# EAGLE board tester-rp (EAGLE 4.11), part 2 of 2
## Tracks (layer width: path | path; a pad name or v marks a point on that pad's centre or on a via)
A1  (via drill 0.61)
  Top 0.254: A1-K1.1 66.04,56.5 67.31,55.23 JP3.1 | v74.93,51.42 74.93,48.24 SIDE1.10
  Bottom 0.254: 62.87,51.42 62.87,53.32 66.67,53.32 JP3.1 | 62.87,51.42 62.87,14.59 71.12,6.33 IN1-2.1 | 62.87,51.42 v74.93,51.42
A2  (via drill 0.61)
  Top 0.254: A2-K2.1 99.06,26.02 100.33,24.75 JP4.1 100.33,22.21 100.33,19.04 101.6,17.77 SIDE2.2 | v101.6,40.62 101.6,46.34 103.5,46.34 104.14,46.98 104.14,55.23 105.41,56.5 105.41,60.95 100.33,60.95 97.79,63.48 97.79,66.66 96.52,67.93 96.52,74.92 97.79,76.19 R1.2
  Bottom 0.254: v101.6,40.62 101.6,36.81 104.78,36.81 105.41,36.18 105.41,29.2 100.97,29.2 99.69,27.92 A2-K2.1
B1
  Top 0.254: A1-K1.2 68.58,56.5 69.85,55.23 JP3.2 69.85,52.69 69.85,48.24 SIDE1.6 69.85,46.98 68.58,45.7 68.58,44.44 72.39,40.62 72.39,7.6 73.66,6.33 IN1-2.3
B2
  Top 0.254: A2-K2.2 101.6,26.02 102.87,24.75 JP4.2 102.87,22.21 102.87,19.04 104.14,17.77 SIDE2.4
C1
  Top 0.254: A1-K1.3 71.12,56.5 72.39,55.23 JP3.3 72.39,52.69 71.12,51.42 71.12,45.07 | SIDE1.1 65.41,45.07 66.67,45.07 SIDE1.3 | 71.12,45.07 70.48,45.07 SIDE1.5 | 71.12,45.07 71.75,45.07 SIDE1.7 73.03,45.07 74.3,45.07 SIDE1.9 74.93,44.44 74.93,7.6 76.2,6.33 IN1-2.5 | SIDE1.17 85.72,45.07 87,45.07 SIDE1.19 88.27,45.07 89.53,45.07 SIDE1.21 90.81,45.07 92.08,45.07 SIDE1.23 93.34,45.07 94.62,45.07 SIDE1.25 95.89,45.07 97.16,45.07 SIDE1.27 98.43,45.07 99.69,45.07 SIDE1.29 | SIDE1.33 104.78,45.07 103.5,45.07 SIDE1.31
  Bottom 0.254: SIDE1.5 69.22,45.07 67.95,45.07 SIDE1.3 | SIDE1.9 75.56,45.07 76.84,45.07 SIDE1.11 78.11,45.07 79.38,45.07 SIDE1.13 80.65,45.07 81.92,45.07 SIDE1.15 83.19,45.07 84.45,45.07 SIDE1.17 | SIDE1.31 102.23,45.07 100.97,45.07 SIDE1.29
C2
  Top 0.254: A2-K2.3 104.14,26.02 105.41,24.75 JP4.3 105.41,22.21 105.41,14.59 | 105.41,14.59 104.78,14.59 SIDE2.3 | 105.41,14.59 106.05,14.59 SIDE2.5 107.31,14.59 108.59,14.59 SIDE2.7 109.86,14.59 111.12,14.59 SIDE2.9 | SIDE2.15 120.02,14.59 121.28,14.59 SIDE2.17 122.56,14.59 123.83,14.59 SIDE2.19 125.09,14.59 126.36,14.59 SIDE2.21 127.64,14.59 128.91,14.59 SIDE2.23 | SIDE2.25 132.72,14.59 133.99,14.59 SIDE2.27 135.25,14.59 136.53,14.59 SIDE2.29 137.8,14.59 139.06,14.59 SIDE2.31
  Bottom 0.254: SIDE2.1 102.23,14.59 103.5,14.59 SIDE2.3 | SIDE2.9 112.4,14.59 113.66,14.59 SIDE2.11 114.94,14.59 116.2,14.59 SIDE2.13 117.47,14.59 118.75,14.59 SIDE2.15 | SIDE2.25 131.44,14.59 130.18,14.59 SIDE2.23 | SIDE2.33 141.61,14.59 140.34,14.59 SIDE2.31
D1
  Top 0.254: 73.66,56.5 74.93,55.23 JP3.4 74.93,52.69 76.2,51.42 76.2,44.44 77.47,43.16 77.47,7.6 78.74,6.33 IN1-2.7 | 73.66,56.5 A1-K1.4 73.66,56.5 | 73.66,56.5 73.66,49.52 72.39,48.24 SIDE1.8
D2  (via drill 0.61)
  Top 0.254: A2-K2.4 106.68,26.02 107.95,24.75 JP4.4 107.95,22.21 106.68,20.94 106.68,17.77 SIDE2.6 | v100.33,15.86 100.33,7.6 99.06,6.33 IN3-4.3
  Bottom 0.254: v100.33,15.86 100.33,18.4 104.78,18.4 106.05,17.13 SIDE2.6
E1
  Top 0.254: IN1-2.2 71.12,8.88 63.5,16.49 63.5,57.77 65.41,59.68 76.2,59.68 76.2,59.04 A1-K1.5 76.2,56.5 77.47,55.23 JP3.5 77.47,52.69 77.47,48.24 SIDE1.12
E2  (via drill 0.61)
  Top 0.254: A2-K2.5 109.22,26.02 110.49,24.75 JP4.5 110.49,22.21 109.22,20.94 109.22,17.77 SIDE2.8 | v102.87,11.41 102.87,7.6 101.6,6.33 IN3-4.5
  Bottom 0.254: v102.87,11.41 105.41,13.95 105.41,15.86 107.31,15.86 108.59,17.13 SIDE2.8
F1
  Top 0.254: A1-K1.6 78.74,56.5 80.01,55.23 JP3.6 80.01,52.69 80.01,48.24 SIDE1.14
  Bottom 0.254: IN1-2.4 73.03,8.24 63.5,17.77 63.5,50.15 76.2,50.15 79.38,53.32 JP3.6
F2
  Top 0.254: A2-K2.6 111.76,26.02 113.03,24.75 JP4.6 113.03,22.21 111.76,20.94 111.76,17.77 SIDE2.10
  Bottom 0.254: IN3-4.7 104.14,6.33 105.41,7.6 105.41,12.68 109.22,12.68 110.49,13.95 110.49,17.13 111.12,17.13 SIDE2.10
GND  (via drill 0.61)
  Top 0.305: CORE-IO.11 78.11,81.9 76.2,83.81 CORE-IO.10 76.2,85.08 76.2,86.98 | 76.2,86.98 76.2,91.43 73.66,93.97 71.12,93.97 71.12,97.14 72.39,98.41 72.39,100.32 | 72.39,100.32 72.39,115.56 71.12,116.83 BYP1.2 | 72.39,100.32 v73.03,100.32 | C1.2 97.79,86.35 96.52,87.62 96.52,99.68 IC3.7 | A2-K2.16 104.14,36.18 105.41,37.45 JP2.3 | L1-V1.12 106.68,66.66 105.41,67.93 JP1.16 105.41,70.47 104.14,71.74 104.14,88.89 102.23,88.89 100.97,87.62 IC9.7 | BYP7.2 125.09,76.82 125.09,60.95 123.83,59.68 IC7.7 123.19,58.41 v123.19,43.16 | v78.74,86.98 76.2,86.98
  Bottom 0.305: 73.03,100.95 80.01,100.95 81.28,99.68 IC2.7 | 73.03,100.95 72.39,100.95 71.12,99.68 IC1.7 | 81.92,118.73 73.03,118.73 71.75,117.46 BYP1.2 | 81.92,118.73 83.19,117.46 BYP2.2 | 94.62,118.73 95.89,117.46 BYP3.2 | 81.92,118.73 94.62,118.73 | 107.31,118.73 108.59,117.46 BYP4.2 | 94.62,118.73 107.31,118.73 | 120.02,118.73 121.28,117.46 BYP5.2 | 107.31,118.73 120.02,118.73 | 120.02,118.73 132.72,118.73 133.99,117.46 BYP6.2 | v73.03,100.32 73.03,100.95 | IC6.7 132.08,99.68 130.81,98.41 123.19,98.41 121.92,99.68 IC5.7 119.38,99.68 118.11,98.41 113.03,98.41 111.76,99.68 109.22,99.68 IC4.7 106.68,99.68 105.41,98.41 97.79,98.41 96.52,99.68 IC3.7 | C1.2 98.43,85.71 99.06,86.35 99.69,86.35 IC9.7 99.69,86.98 v78.74,86.98 | 84.45,15.22 83.82,15.22 BYP10.2 | 84.45,15.22 89.53,15.22 POWER.1 | 84.45,15.22 103.5,34.27 A2-K2.16 | 133.35,83.17 133.35,86.35 118.11,86.35 BYP9.2 | 133.35,83.17 133.35,81.27 137.16,77.46 BYP8.2 | IC8.7 134.62,59.04 133.35,60.31 125.73,60.31 124.46,59.04 IC7.7 122.56,59.68 111.12,59.68 106.68,64.12 L1-V1.12 | 133.35,83.17 128.91,83.17 128.27,82.54 128.27,80 127,80 124.46,77.46 BYP7.2 | v123.19,43.16 110.49,43.16 109.86,42.53 107.95,42.53 105.41,39.99 JP2.3
H1
  Top 0.254: A1-K1.7 81.28,56.5 82.55,55.23 JP3.7 82.55,52.69 82.55,48.24 SIDE1.16
  Bottom 0.254: IN1-2.6 76.2,7.6 74.93,6.33 74.93,4.43 70.48,4.43 62.23,12.68 62.23,55.87 79.38,55.87 80.65,57.13 A1-K1.7
H2
  Top 0.254: A2-K2.7 114.3,26.02 115.57,24.75 JP4.7 115.57,22.21 115.57,17.13 | 115.57,17.13 115.57,13.95 113.03,11.41 113.03,4.43 98.43,4.43 97.79,5.07 97.79,6.33 96.52,7.6 IN3-4.2 | 115.57,17.13 114.94,17.13 SIDE2.12
J1
  Top 0.254: 83.82,56.5 85.09,55.23 JP3.8 | 83.82,56.5 A1-K1.8 83.82,56.5 | 83.82,50.78 83.82,56.5 | 83.82,50.78 83.82,46.98 83.19,46.34 81.92,46.34 81.28,45.7 81.28,11.41 78.74,8.88 IN1-2.8 | 83.82,50.78 87,47.61 SIDE1.20
J2
  Top 0.254: A2-K2.8 116.84,26.02 118.11,24.75 JP4.8 118.11,22.21 118.11,19.04 116.84,17.77 SIDE2.14
  Bottom 0.254: IN3-4.4 99.06,8.88 99.06,12.68 98.43,13.32 98.43,25.38 114.94,25.38 116.2,26.65 A2-K2.8
K1  (via drill 0.61)
  Top 0.254: A1-K1.9 86.36,56.5 87.63,55.23 JP3.9 | v85.09,43.16 85.09,15.22 82.55,12.68 82.55,7.6 81.28,6.33 IN1-2.9
  Bottom 0.254: v85.09,43.16 86.36,44.44 86.36,46.98 85.09,46.98 SIDE1.18 85.72,47.61 87,48.88 87.63,48.88 87.63,52.69 JP3.9
K2
  Top 0.254: IN3-4.6 101.6,8.88 101.6,12.68 102.87,13.95 102.87,17.77 101.6,19.04 101.6,24.75 100.33,26.02 100.33,28.56 100.97,29.2 119.38,29.2 119.38,28.56 A2-K2.9 119.38,26.02 120.65,24.75 JP4.9 120.02,22.84 120.02,18.4 119.38,17.77 SIDE2.16
L1  (via drill 0.61)
  Top 0.254: L1-V1.1 91.44,56.5 90.17,55.23 JP3.10 90.17,52.69 92.71,50.15 92.71,48.24 SIDE1.24 | v90.17,6.97 91.44,8.24 v91.44,43.8
  Bottom 0.254: v90.17,6.97 85.72,6.97 84.45,5.7 IN1-2.11 | v91.44,43.8 91.44,47.61 92.08,47.61 SIDE1.24
L2
  Top 0.254: L2-V2.1 124.46,26.02 123.19,24.75 JP4.10 123.19,22.21 123.19,19.04 121.92,17.77 SIDE2.18
  Bottom 0.254: IN3-4.8 104.14,8.88 99.06,13.95 99.06,21.57 121.28,21.57 122.56,22.84 JP4.10
M1  (via drill 0.61)
  Top 0.254: L1-V1.2 93.98,56.5 92.71,55.23 JP3.11 92.71,52.69 97.16,48.24 97.16,47.61 SIDE1.28 | v87.63,35.55 87.63,7.6 86.36,6.33 IN1-2.13
  Bottom 0.254: v87.63,35.55 96.52,44.44 96.52,47.61 97.16,47.61 SIDE1.28
M2
  Top 0.254: L2-V2.2 127,26.02 125.73,24.75 JP4.11 125.73,22.21 125.73,19.04 124.46,17.77 SIDE2.20
  Bottom 0.254: IN3-4.9 107.31,5.7 109.86,3.16 139.06,3.16 143.51,7.6 143.51,21.57 127.64,21.57 126.36,22.84 JP4.11
MR\  (via drill 0.61)
  Top 0.254: v102.87,83.81 102.87,80.63 IC9.9
  Bottom 0.254: IC9.9 103.5,80 104.78,81.27 106.05,81.27 107.31,80 IC9.11 | v102.87,83.81 97.79,83.81 95.89,85.71 MR\.1
N1  (via drill 0.61)
  Top 0.254: L1-V1.3 96.52,56.5 95.25,55.23 JP3.12 | v93.98,43.8 93.98,5.7 89.53,5.7 IN1-2.15
  Bottom 0.254: 93.98,48.88 93.98,53.32 94.62,53.32 JP3.12 | v93.98,43.8 93.98,48.88 | 93.98,48.88 90.81,48.88 90.17,48.24 SIDE1.22
N2
  Top 0.254: L2-V2.3 129.54,26.02 128.27,24.75 JP4.12 128.27,22.21 127,20.94 127,17.77 SIDE2.22
  Bottom 0.254: IN3-4.11 109.22,6.33 110.49,7.6 110.49,11.41 123.19,11.41 125.73,13.95 125.73,17.13 126.36,17.13 SIDE2.22
N$1  (via drill 0.61)
  Top 0.254: v109.22,88.89 109.22,81.9 110.49,80.63 IC9.12
  Bottom 0.254: v109.22,88.89 106.68,88.89 106.68,85.71 106.05,85.08 104.78,85.08 103.5,86.35 IC9.6
N$2
  Bottom 0.254: IC9.4 108.59,86.35 109.86,86.35 IC9.3
N$5  (via drill 0.61)
  Top 0.254: v105.41,83.17 105.41,80.63 IC9.10
  Bottom 0.254: v105.41,83.17 104.78,82.54 100.33,82.54 98.43,80.63 C1.1 | R1.1 107.31,76.82 106.05,78.09 105.41,78.09 IC9.10
N$26
  Bottom 0.254: A5.L1 36.2,104.12 36.83,103.49 47.62,103.49 48.26,104.12 A9.L1
N$33
  Bottom 0.254: A5.L2 29.85,105.4 30.48,106.03 41.28,106.03 41.91,105.4 A9.L2
N$34
  Bottom 0.254: A5.M1 39.37,100.95 40.01,100.32 50.8,100.32 51.44,100.95 A9.M1
N$35
  Bottom 0.254: A5.M2 33.02,102.22 33.66,102.86 44.45,102.86 45.09,102.22 A9.M2
N$36
  Bottom 0.254: A5.N1 36.2,97.78 36.83,97.14 47.62,97.14 48.26,97.78 A9.N1
N$49
  Bottom 0.254: A5.N2 29.85,99.05 30.48,99.68 41.28,99.68 41.91,99.05 A9.N2
N$50
  Bottom 0.254: A5.P1 39.37,94.6 40.01,93.97 50.8,93.97 51.44,94.6 A9.P1
N$51
  Bottom 0.254: A5.P2 33.02,95.87 33.66,96.51 44.45,96.51 45.09,95.87 A9.P2
N$52
  Bottom 0.254: A5.R1 36.2,91.43 36.83,90.79 47.62,90.79 48.26,91.43 A9.R1
N$53
  Top 0.254: RN3.9 69.85,97.14 71.75,99.05 71.75,113.02 70.48,114.29 IC1.1 69.85,115.56 69.85,120.64 71.12,121.91 OUT1-2.1
N$54  (via drill 0.61)
  Top 0.254: 73.03,107.3 73.03,122.54 OUT1-2.3 | 73.03,107.3 73.03,104.76 74.3,103.49 74.3,99.05 72.39,97.14 RN3.8 | 73.03,107.3 v73.66,107.3
  Bottom 0.254: v73.66,107.3 71.12,107.3 IC1.4
N$55  (via drill 0.61)
  Top 0.254: 74.93,104.76 74.93,120.64 76.2,121.91 OUT1-2.5 | 74.93,104.76 74.93,97.14 RN3.7 | 74.93,104.76 v74.3,104.76
  Bottom 0.254: v74.3,104.76 76.2,104.76 IC1.10
N$56
  Top 0.254: RN3.6 77.47,97.14 75.56,99.05 75.56,110.48 76.84,111.75 IC1.13 78.11,113.02 79.38,114.29 79.38,121.27 78.74,121.91 OUT1-2.7
N$57
  Top 0.254: IC1.2 69.22,113.02 67.95,114.29 67.95,120 69.85,121.91 69.85,123.18 71.12,124.45 OUT1-2.2
N$58  (via drill 0.61)
  Top 0.254: v67.31,106.03 v67.31,120.64
  Bottom 0.254: v67.31,106.03 68.58,104.76 IC1.5 | v67.31,120.64 70.48,123.81 71.75,123.81 73.03,125.08 OUT1-2.4
N$59  (via drill 0.61)
  Top 0.254: v63.5,100.95 62.87,101.59 62.87,118.1 69.85,125.08 69.85,125.72 70.48,126.35 76.2,126.35 76.2,125.72 OUT1-2.6
  Bottom 0.254: v63.5,100.95 71.12,100.95 71.75,101.59 75.56,101.59 76.2,102.22 IC1.9
N$60
  Top 0.254: IC1.12 78.11,110.48 80.01,112.38 80.01,123.18 78.74,124.45 OUT1-2.8
N$61  (via drill 0.61)
  Top 0.254: OUT5-6.3 124.46,121.91 124.46,111.11 v123.83,110.48 123.19,109.84 123.19,97.14 RN4.8
  Bottom 0.254: v123.83,110.48 121.28,107.94 IC5.4
N$62  (via drill 0.61)
  Top 0.254: RN3.3 85.09,97.14 87.63,99.68 v87.63,106.03 87.63,108.57 91.44,108.57 92.08,109.21 92.08,111.11 88.9,111.11 87.63,112.38 87.63,119.37 v88.27,120
  Bottom 0.254: v87.63,106.03 88.9,104.76 IC2.10 | v88.27,120 86.36,121.91 OUT1-2.13
N$63
  Top 0.254: RN3.4 82.55,97.14 80.65,99.05 80.65,105.4 81.92,106.67 IC2.4 83.19,107.94 85.09,109.84 85.09,118.1 84.45,118.73 84.45,121.27 83.82,121.91 OUT1-2.11
N$64
  Top 0.254: 80.65,114.92 80.65,122.54 OUT1-2.9 | 80.65,114.92 80.65,111.75 79.38,110.48 79.38,97.78 80.01,97.14 RN3.5 | 80.65,114.92 81.28,114.92 IC2.1
N$65
  Top 0.254: IC2.2 83.19,113.02 84.45,114.29 84.45,115.56 83.82,116.19 82.55,116.19 82.55,123.18 81.28,124.45 OUT1-2.10
N$66  (via drill 0.61)
  Top 0.254: v66.04,103.49 v66.04,114.92
  Bottom 0.254: v66.04,103.49 80.01,103.49 81.28,104.76 IC2.5 | v66.04,114.92 72.39,121.27 81.92,121.27 82.55,121.91 82.55,125.08 83.19,125.08 OUT1-2.12
N$67  (via drill 0.61)
  Top 0.254: v86.36,102.22 v86.36,120.64
  Bottom 0.254: v86.36,102.22 88.9,102.22 IC2.9 | v86.36,120.64 85.09,121.91 85.09,125.08 85.72,125.08 OUT1-2.14
N$68
  Top 0.254: IC2.12 88.9,109.84 87,111.75 87,120 87.63,120.64 87.63,123.18 88.9,124.45 OUT1-2.16
N$69
  Bottom 0.254: A5.R2 29.85,92.7 30.48,93.33 41.28,93.33 41.91,92.7 A9.R2
N$70
  Bottom 0.254: A5.S1 39.37,88.25 40.01,87.62 50.8,87.62 51.44,88.25 A9.S1
N$71
  Bottom 0.254: A5.S2 33.02,89.52 33.66,90.16 44.45,90.16 45.09,89.52 A9.S2
N$72
  Bottom 0.254: A5.T1 36.2,85.08 36.83,84.44 47.62,84.44 48.26,85.08 A9.T1
N$73
  Bottom 0.254: A5.T2 29.85,86.35 30.48,86.98 41.28,86.98 41.91,86.35 A9.T2
N$74
  Bottom 0.254: A5.U1 39.37,81.9 40.01,81.27 50.8,81.27 51.44,81.9 A9.U1
N$75
  Bottom 0.254: A5.U2 33.02,83.17 33.66,83.81 44.45,83.81 45.09,83.17 A9.U2
N$76
  Bottom 0.254: A5.V1 36.2,78.73 36.83,78.09 47.62,78.09 48.26,78.73 A9.V1
N$81
  Bottom 0.254: A5.V2 29.85,80 30.48,80.63 41.28,80.63 41.91,80 A9.V2
N$82
  Bottom 0.254: A5.A1 39.37,132.7 40.01,132.06 50.8,132.06 51.44,132.7 A9.A1
N$83
  Bottom 0.254: A5.A2 33.02,133.97 33.66,134.6 44.45,134.6 45.09,133.97 A9.A2
N$84
  Bottom 0.254: A5.B1 36.2,129.53 36.83,128.89 47.62,128.89 48.26,129.53 A9.B1
N$85
  Bottom 0.254: A5.B2 29.85,130.79 30.48,131.43 41.28,131.43 41.91,130.79 A9.B2
N$86
  Bottom 0.254: A5.C1 39.37,126.35 40.01,125.72 50.8,125.72 51.44,126.35 A9.C1
N$87
  Bottom 0.254: A5.C2 33.02,127.62 33.66,128.25 44.45,128.25 45.09,127.62 A9.C2
N$88
  Bottom 0.254: A5.D1 36.2,123.18 36.83,122.54 47.62,122.54 48.26,123.18 A9.D1
N$89
  Bottom 0.254: A5.D2 29.85,124.45 30.48,125.08 41.28,125.08 41.91,124.45 A9.D2
N$90
  Bottom 0.254: A5.E1 39.37,120 40.01,119.37 50.8,119.37 51.44,120 A9.E1
N$91
  Bottom 0.254: A5.E2 33.02,121.27 33.66,121.91 44.45,121.91 45.09,121.27 A9.E2
N$92
  Bottom 0.254: A5.F1 36.2,116.83 36.83,116.19 47.62,116.19 48.26,116.83 A9.F1
N$93
  Bottom 0.254: A5.F2 29.85,118.1 30.48,118.73 41.28,118.73 41.91,118.1 A9.F2
N$95
  Bottom 0.254: A5.H1 39.37,113.65 40.01,113.02 50.8,113.02 51.44,113.65 A9.H1
N$96
  Bottom 0.254: A5.H2 33.02,114.92 33.66,115.56 44.45,115.56 45.09,114.92 A9.H2
N$97
  Bottom 0.254: A5.J1 36.2,110.48 36.83,109.84 47.62,109.84 48.26,110.48 A9.J1
N$98
  Bottom 0.254: A5.J2 29.85,111.75 30.48,112.38 41.28,112.38 41.91,111.75 A9.J2
N$99
  Bottom 0.254: A5.K1 39.37,107.3 40.01,106.67 50.8,106.67 51.44,107.3 A9.K1
N$100
  Bottom 0.254: A5.K2 33.02,108.57 33.66,109.21 44.45,109.21 45.09,108.57 A9.K2
N$113
  Bottom 0.254: A6.L1 10.8,104.12 11.43,103.49 22.23,103.49 22.86,104.12 A7.L1
N$114
  Bottom 0.254: A6.L2 4.45,105.4 5.08,106.03 15.88,106.03 16.51,105.4 A7.L2
N$115
  Bottom 0.254: A6.M1 13.97,100.95 14.61,100.32 25.4,100.32 26.04,100.95 A7.M1
N$116
  Bottom 0.254: A6.M2 7.62,102.22 8.26,102.86 19.05,102.86 19.69,102.22 A7.M2
N$117
  Bottom 0.254: A6.N1 10.8,97.78 11.43,97.14 22.23,97.14 22.86,97.78 A7.N1
N$118
  Bottom 0.254: A6.N2 4.45,99.05 5.08,99.68 15.88,99.68 16.51,99.05 A7.N2
N$119
  Bottom 0.254: A6.P1 13.97,94.6 14.61,93.97 25.4,93.97 26.04,94.6 A7.P1
N$120
  Bottom 0.254: A6.P2 7.62,95.87 8.26,96.51 19.05,96.51 19.69,95.87 A7.P2
N$121
  Bottom 0.254: A6.R1 10.8,91.43 11.43,90.79 22.23,90.79 22.86,91.43 A7.R1
N$122
  Bottom 0.254: A6.R2 4.45,92.7 5.08,93.33 15.88,93.33 16.51,92.7 A7.R2
N$123
  Bottom 0.254: A6.S1 13.97,88.25 14.61,87.62 25.4,87.62 26.04,88.25 A7.S1
N$137
  Bottom 0.254: A6.S2 7.62,89.52 8.26,90.16 19.05,90.16 19.69,89.52 A7.S2
N$138  (via drill 0.61)
  Top 0.254: v125.09,109.21 125.09,104.12 126.36,102.86 126.36,99.05 128.27,97.14 RN4.6 | OUT5-6.7 129.54,121.91 130.18,121.27 130.18,114.29 128.91,113.02 IC5.13
  Bottom 0.254: v125.09,109.21 127.64,111.75 IC5.13
N$139  (via drill 0.61)
  Top 0.254: v85.72,99.05 85.09,99.68 85.09,102.86 85.72,103.49 85.72,120 85.09,120.64 85.09,125.72 85.72,126.35 90.17,126.35 90.17,124.45 88.9,123.18 OUT1-2.15 88.9,121.91 92.08,118.73 92.08,114.29 90.81,113.02 IC2.13
  Bottom 0.254: v85.72,99.05 87.63,97.14 RN3.2
N$140
  Top 0.254: IC5.2 121.28,113.02 123.19,114.92 123.19,123.18 121.92,124.45 OUT5-6.2
N$141  (via drill 0.61)
  Top 0.254: v130.18,108.57 130.81,109.21 130.81,125.72 130.18,126.35 124.46,126.35 124.46,125.72 OUT5-6.4
  Bottom 0.254: v130.18,108.57 125.73,108.57 121.92,104.76 IC5.5
N$142
  Top 0.254: IC5.9 127.64,102.86 126.36,104.12 126.36,116.19 125.73,116.83 125.73,119.37 128.27,121.91 128.27,123.18 127,124.45 OUT5-6.6
N$143  (via drill 0.61)
  Top 0.254: v135.89,113.65 v135.89,123.81
  Bottom 0.254: v135.89,113.65 132.08,113.65 128.91,110.48 IC5.12 | v135.89,123.81 131.44,123.81 130.18,125.08 OUT5-6.8
N$144  (via drill 0.61)
  Top 0.254: v135.89,103.49 135.89,97.14 RN4.3 | v139.06,108.57 139.06,106.67 140.34,105.4 IC6.10
  Bottom 0.254: v135.89,103.49 137.16,104.76 139.7,104.76 IC6.10 | v139.06,108.57 144.78,108.57 144.78,116.83 142.24,119.37 140.97,119.37 137.8,122.54 OUT5-6.13
N$145
  Top 0.254: RN4.4 133.35,97.14 131.44,99.05 131.44,105.4 132.72,106.67 IC6.4
  Bottom 0.254: OUT5-6.11 135.25,122.54 139.06,118.73 141.61,118.73 142.88,117.46 142.88,113.65 139.7,113.65 133.99,107.94 IC6.4
N$146  (via drill 0.61)
  Top 0.254: v137.16,119.37 137.16,93.97 132.72,93.97 131.44,95.23 RN4.5 | IC6.1 132.72,115.56 132.08,116.19 132.08,121.91 OUT5-6.9
  Bottom 0.254: v137.16,119.37 135.25,121.27 133.99,121.27 132.72,122.54 OUT5-6.9
N$147
  Top 0.254: IC6.2 133.99,113.02 135.25,114.29 135.25,115.56 134.62,116.19 133.35,116.19 133.35,123.18 132.08,124.45 OUT5-6.10
N$148
  Top 0.254: IC6.9 140.34,102.86 137.8,105.4 137.8,118.73 138.43,119.37 138.43,123.18 137.16,124.45 OUT5-6.14
N$149  (via drill 0.61)
  Top 0.254: v143.51,112.38 142.88,113.02 142.88,122.54 140.34,125.08 OUT5-6.16
  Bottom 0.254: v143.51,112.38 141.61,110.48 IC6.12
N$150
  Top 0.254: RN4.9 120.65,97.14 118.75,99.05 118.75,105.4 119.38,106.03 122.56,106.03 122.56,110.48 121.92,111.11 118.75,111.11 118.75,113.02 120.02,114.29 IC5.1 120.65,115.56 120.65,120.64 121.92,121.91 OUT5-6.1
N$151  (via drill 0.61)
  Top 0.254: RN4.7 125.73,97.14 125.73,102.22 v125.09,102.86 123.83,104.12 123.83,109.21 125.09,110.48 125.09,120 127,121.91 OUT5-6.5
  Bottom 0.254: v125.09,102.86 127,104.76 IC5.10
N$152  (via drill 0.61)
  Top 0.254: v135.89,112.38 135.89,107.3 133.99,105.4 IC6.5 | v141.61,117.46 140.97,118.1 140.97,123.18 140.34,123.81 139.06,123.81 138.43,124.45 138.43,125.72 137.8,126.35 134.62,126.35 134.62,125.72 OUT5-6.12
  Bottom 0.254: v135.89,112.38 139.7,116.19 140.34,116.19 v141.61,117.46
N$153
  Top 0.254: RN4.2 138.43,97.14 139.06,97.78 139.06,100.32 139.7,100.95 142.88,100.95 142.88,110.48 141.61,111.75 IC6.13 140.34,113.02 138.43,114.92 138.43,118.1 139.06,118.73 139.06,121.27 139.7,121.91 OUT5-6.15
N$154
  Top 0.254: RN1.8 97.79,93.33 97.79,104.76 95.89,106.67 IC3.4 95.89,107.94 98.43,110.48 98.43,121.27 99.06,121.91 OUT3-4.3
N$155  (via drill 0.61)
  Top 0.254: RN1.6 102.87,93.33 104.78,95.23 104.78,110.48 103.5,111.75 IC3.13 | v115.57,121.27 117.47,119.37 117.47,111.75 116.84,111.11 114.3,111.11 113.66,110.48 113.66,94.6 v114.3,93.97
  Bottom 0.254: v115.57,121.27 106.05,121.27 104.78,122.54 OUT3-4.7 | v114.3,93.97 104.78,93.97 103.5,92.7 RN1.6
N$156
  Top 0.254: IC3.2 95.89,113.02 97.79,114.92 97.79,123.18 96.52,124.45 OUT3-4.2
N$157  (via drill 0.61)
  Top 0.254: v92.08,106.03 92.71,106.67 92.71,123.18 95.89,126.35 99.06,126.35 99.06,125.72 OUT3-4.4
  Bottom 0.254: v92.08,106.03 92.71,106.03 93.98,104.76 IC3.5
N$158  (via drill 0.61)
  Top 0.254: v109.86,111.11 106.05,111.11 106.05,118.73 102.87,121.91 102.87,123.18 101.6,124.45 OUT3-4.6
  Bottom 0.254: v109.86,111.11 106.05,111.11 106.05,105.4 103.5,102.86 IC3.9
N$159  (via drill 0.61)
  Top 0.254: v110.49,113.65 110.49,123.18 109.86,123.81 108.59,123.81 107.95,124.45 107.95,125.72 107.31,126.35 104.14,126.35 104.14,125.72 OUT3-4.8
  Bottom 0.254: v110.49,113.65 106.68,113.65 103.5,110.48 IC3.12
N$160  (via drill 0.61)
  Top 0.254: v110.49,103.49 110.49,93.33 RN1.3 | v119.38,117.46 119.38,126.35 111.12,126.35 110.49,125.72 110.49,124.45 111.76,123.18 OUT3-4.13
  Bottom 0.254: v110.49,103.49 111.76,104.76 114.3,104.76 IC4.10 116.84,104.76 118.75,106.67 118.75,109.21 116.84,111.11 113.66,111.11 113.66,115.56 114.3,116.19 114.94,116.19 115.57,116.83 118.75,116.83 v119.38,117.46
N$161  (via drill 0.61)
  Top 0.254: RN1.4 107.95,93.33 106.05,95.23 106.05,105.4 107.31,106.67 IC4.4 | v112.4,120 112.4,111.75 v110.49,109.84
  Bottom 0.254: v112.4,120 118.11,120 118.11,121.27 115.57,123.81 111.12,123.81 109.86,122.54 OUT3-4.11 | v110.49,109.84 108.59,107.94 IC4.4
N$162  (via drill 0.61)
  Top 0.254: v104.78,113.65 105.41,113.02 105.41,93.33 RN1.5 | OUT3-4.9 106.68,121.91 107.31,121.27 107.31,115.56 IC4.1
  Bottom 0.254: v104.78,113.65 106.05,114.92 106.68,114.92 IC4.1
N$163
  Top 0.254: IC4.2 108.59,113.02 109.86,114.29 109.86,115.56 109.22,116.19 107.95,116.19 107.95,123.18 106.68,124.45 OUT3-4.10
N$164  (via drill 0.61)
  Top 0.254: v117.47,108.57 117.47,104.12 116.2,102.86 IC4.9 | v111.12,111.75 111.76,112.38 111.76,119.37 111.12,120 113.03,121.91 113.03,123.18 111.76,124.45 OUT3-4.14
  Bottom 0.254: v117.47,108.57 114.3,108.57 v111.12,111.75
N$165
  Top 0.254: IC4.12 116.84,109.84 118.11,111.11 118.11,121.91 114.94,125.08 OUT3-4.16
N$166
  Top 0.254: RN1.9 95.25,93.33 93.34,95.23 93.34,113.02 94.62,114.29 IC3.1 95.25,115.56 95.25,120.64 96.52,121.91 OUT3-4.1
N$167
  Top 0.254: RN1.7 100.33,93.33 100.97,93.97 100.97,102.86 102.23,104.12 IC3.10 102.23,105.4 100.33,107.3 100.33,120.64 101.6,121.91 OUT3-4.5
N$168  (via drill 0.61)
  Top 0.254: v108.59,97.78 109.86,99.05 109.86,102.86 108.59,104.12 IC4.5 | v99.06,103.49 99.06,120.64 100.33,121.91 100.33,125.72 101.6,126.98 109.22,126.98 109.22,125.72 OUT3-4.12
  Bottom 0.254: v108.59,97.78 94.62,97.78 93.34,99.05 93.34,100.32 93.98,100.95 96.52,100.95 v99.06,103.49
N$169
  Top 0.254: 113.03,111.11 113.03,93.33 RN1.2 | 113.03,111.11 114.3,112.38 IC4.13 | 113.03,111.11 113.03,118.1 113.66,118.73 113.66,121.27 114.3,121.91 OUT3-4.15
N$170  (via drill 0.61)
  Top 0.254: RN2.8 127,55.23 v127,66.66 127,81.27 OUT7-8.3
  Bottom 0.254: v127,66.66 124.46,66.66 IC7.4
N$171
  Top 0.254: RN2.6 132.08,55.23 132.72,55.87 132.72,64.76 132.08,65.39 128.91,65.39 128.91,69.84 130.18,71.11 IC7.13 131.44,72.38 132.72,73.65 132.72,80.63 132.08,81.27 OUT7-8.7
N$172
  Top 0.254: IC7.2 122.56,72.38 121.28,73.65 121.28,80.63 124.46,83.81 OUT7-8.2
N$173  (via drill 0.61)
  Top 0.254: v117.47,64.12 116.2,65.39 116.2,77.46 116.84,78.09 v116.84,81.9
  Bottom 0.254: v117.47,64.12 121.92,64.12 IC7.5 | v116.84,81.9 118.11,83.17 125.09,83.17 126.36,84.44 OUT7-8.4
N$174  (via drill 0.61)
  Top 0.254: v113.66,62.85 113.03,63.48 113.03,76.82 111.76,78.09 v111.76,81.9
  Bottom 0.254: v113.66,62.85 128.27,62.85 129.54,61.58 IC7.9 | v111.76,81.9 114.3,84.44 122.56,84.44 123.83,85.71 127.64,85.71 128.91,84.44 OUT7-8.6
N$175
  Top 0.254: IC7.12 131.44,69.84 133.35,71.74 133.35,82.54 132.08,83.81 OUT7-8.8
N$176
  Top 0.254: RN2.3 139.7,55.23 141.61,57.13 141.61,62.21 142.88,63.48 IC8.10 142.88,64.76 139.7,67.93 139.7,81.27 OUT7-8.13
N$177  (via drill 0.61)
  Top 0.254: RN2.4 137.8,54.59 v137.8,62.85 138.43,63.48 138.43,80 137.16,81.27 OUT7-8.11
  Bottom 0.254: v137.8,62.85 137.8,64.76 136.53,66.03 IC8.4
N$178
  Top 0.254: 133.99,74.28 133.99,81.9 OUT7-8.9 | 133.99,74.28 133.99,55.87 134.62,55.23 RN2.5 | 133.99,74.28 134.62,74.28 IC8.1
N$179  (via drill 0.61)
  Top 0.254: v117.47,65.39 117.47,78.09 119.38,80 119.38,86.35 v118.11,87.62 | v133.99,87.62 134.62,86.98 134.62,85.08 OUT7-8.10
  Bottom 0.254: v117.47,65.39 127,65.39 129.54,67.93 132.08,67.93 135.25,71.11 IC8.2 | v118.11,87.62 118.75,86.98 133.35,86.98 v133.99,87.62
N$180  (via drill 0.61)
  Top 0.254: v140.34,64.76 139.06,66.03 139.06,80.63 138.43,81.27 138.43,82.54 139.7,83.81 OUT7-8.14
  Bottom 0.254: v140.34,64.76 142.88,62.21 IC8.9
N$181  (via drill 0.61)
  Top 0.254: v147.32,69.2 146.69,69.84 146.69,79.36 142.24,83.81 OUT7-8.16
  Bottom 0.254: v147.32,69.2 144.78,69.2 IC8.12
N$182
  Top 0.254: 123.19,80 123.19,74.92 IC7.1 | 123.19,80 124.46,81.27 OUT7-8.1 | 123.19,80 125.73,77.46 125.73,56.5 124.46,55.23 RN2.9
N$183
  Top 0.254: 129.54,62.85 130.18,63.48 IC7.10 | 129.54,62.85 128.91,62.21 128.91,55.87 129.54,55.23 RN2.7 | 129.54,62.85 128.27,64.12 128.27,77.46 129.54,78.73 129.54,81.27 OUT7-8.5
N$184
  Top 0.254: IC8.5 136.53,64.76 137.8,66.03 137.8,74.92 137.16,75.55 135.89,75.55 135.89,82.54 137.16,83.81 OUT7-8.12
N$185
  Top 0.254: OUT7-8.15 142.24,81.27 145.42,78.09 145.42,73.65 144.14,72.38 IC8.13
  Bottom 0.254: RN2.2 142.24,55.23 145.42,58.41 145.42,67.93 142.24,67.93 141.61,68.57 141.61,71.74 142.24,71.74 IC8.13
N$186
  Bottom 0.254: A6.T1 10.8,85.08 11.43,84.44 22.23,84.44 22.86,85.08 A7.T1
N$187
  Bottom 0.254: A6.T2 4.45,86.35 5.08,86.98 15.88,86.98 16.51,86.35 A7.T2
N$188
  Bottom 0.254: A6.U1 13.97,81.9 14.61,81.27 25.4,81.27 26.04,81.9 A7.U1
N$189
  Bottom 0.254: A6.U2 7.62,83.17 8.26,83.81 19.05,83.81 19.69,83.17 A7.U2
N$190
  Bottom 0.254: A6.V1 10.8,78.73 11.43,78.09 22.23,78.09 22.86,78.73 A7.V1
N$191
  Bottom 0.254: A6.V2 4.45,80 5.08,80.63 15.88,80.63 16.51,80 A7.V2
N$192
  Bottom 0.254: A6.A1 13.97,132.7 14.61,132.06 25.4,132.06 26.04,132.7 A7.A1
N$193
  Bottom 0.254: A6.A2 7.62,133.97 8.26,134.6 19.05,134.6 19.69,133.97 A7.A2
N$194
  Bottom 0.254: A6.B1 10.8,129.53 11.43,128.89 22.23,128.89 22.86,129.53 A7.B1
N$195
  Bottom 0.254: A6.B2 4.45,130.79 5.08,131.43 15.88,131.43 16.51,130.79 A7.B2
N$196
  Bottom 0.254: A6.C1 13.97,126.35 14.61,125.72 25.4,125.72 26.04,126.35 A7.C1
N$197
  Bottom 0.254: A6.C2 7.62,127.62 8.26,128.25 19.05,128.25 19.69,127.62 A7.C2
N$198
  Bottom 0.254: A6.D1 10.8,123.18 11.43,122.54 22.23,122.54 22.86,123.18 A7.D1
N$199
  Bottom 0.254: A6.D2 4.45,124.45 5.08,125.08 15.88,125.08 16.51,124.45 A7.D2
N$200
  Bottom 0.254: A6.E1 13.97,120 14.61,119.37 25.4,119.37 26.04,120 A7.E1
N$201
  Bottom 0.254: A6.E2 7.62,121.27 8.26,121.91 19.05,121.91 19.69,121.27 A7.E2
N$202
  Bottom 0.254: A6.F1 10.8,116.83 11.43,116.19 22.23,116.19 22.86,116.83 A7.F1
N$203
  Bottom 0.254: A6.F2 4.45,118.1 5.08,118.73 15.88,118.73 16.51,118.1 A7.F2
N$204
  Bottom 0.254: A6.H1 13.97,113.65 14.61,113.02 25.4,113.02 26.04,113.65 A7.H1
N$205
  Bottom 0.254: A6.H2 7.62,114.92 8.26,115.56 19.05,115.56 19.69,114.92 A7.H2
N$206
  Bottom 0.254: A6.J1 10.8,110.48 11.43,109.84 22.23,109.84 22.86,110.48 A7.J1
N$207
  Bottom 0.254: A6.J2 4.45,111.75 5.08,112.38 15.88,112.38 16.51,111.75 A7.J2
N$208
  Bottom 0.254: A6.K1 13.97,107.3 14.61,106.67 25.4,106.67 26.04,107.3 A7.K1
N$209
  Bottom 0.254: A6.K2 7.62,108.57 8.26,109.21 19.05,109.21 19.69,108.57 A7.K2
N$210
  Bottom 0.254: A8.L1 10.8,34.27 11.43,33.64 22.23,33.64 22.86,34.27 A10.L1
N$211
  Bottom 0.254: A8.L2 4.45,35.55 5.08,36.18 15.88,36.18 16.51,35.55 A10.L2
N$212
  Bottom 0.254: A8.M1 13.97,31.1 14.61,30.46 25.4,30.46 26.04,31.1 A10.M1
N$213
  Bottom 0.254: A8.M2 7.62,32.37 8.26,33.01 19.05,33.01 19.69,32.37 A10.M2
N$214
  Bottom 0.254: A8.N1 10.8,27.92 11.43,27.29 22.23,27.29 22.86,27.92 A10.N1
N$215
  Bottom 0.254: A8.N2 4.45,29.2 5.08,29.83 15.88,29.83 16.51,29.2 A10.N2
N$216
  Bottom 0.254: A8.P1 13.97,24.75 14.61,24.11 25.4,24.11 26.04,24.75 A10.P1
N$217
  Bottom 0.254: A8.P2 7.62,26.02 8.26,26.65 19.05,26.65 19.69,26.02 A10.P2
N$218
  Bottom 0.254: A8.R1 10.8,21.57 11.43,20.94 22.23,20.94 22.86,21.57 A10.R1
N$219
  Bottom 0.254: A8.R2 4.45,22.84 5.08,23.48 15.88,23.48 16.51,22.84 A10.R2
N$220
  Bottom 0.254: A8.S1 13.97,18.4 14.61,17.77 25.4,17.77 26.04,18.4 A10.S1
N$221
  Bottom 0.254: A8.S2 7.62,19.67 8.26,20.3 19.05,20.3 19.69,19.67 A10.S2
N$222
  Bottom 0.254: A8.T1 10.8,15.22 11.43,14.59 22.23,14.59 22.86,15.22 A10.T1
N$223
  Bottom 0.254: A8.T2 4.45,16.49 5.08,17.13 15.88,17.13 16.51,16.49 A10.T2
N$224
  Bottom 0.254: A8.U1 13.97,12.05 14.61,11.41 25.4,11.41 26.04,12.05 A10.U1
N$225
  Bottom 0.254: A8.U2 7.62,13.32 8.26,13.95 19.05,13.95 19.69,13.32 A10.U2
N$226
  Bottom 0.254: A8.V1 10.8,8.88 11.43,8.24 22.23,8.24 22.86,8.88 A10.V1
N$227
  Bottom 0.254: A8.V2 4.45,10.14 5.08,10.78 15.88,10.78 16.51,10.14 A10.V2
N$228
  Bottom 0.254: A8.A1 13.97,62.85 14.61,62.21 25.4,62.21 26.04,62.85 A10.A1
N$229
  Bottom 0.254: A8.A2 7.62,64.12 8.26,64.76 19.05,64.76 19.69,64.12 A10.A2
N$230
  Bottom 0.254: A8.B1 10.8,59.68 11.43,59.04 22.23,59.04 22.86,59.68 A10.B1
N$231
  Bottom 0.254: A8.B2 4.45,60.95 5.08,61.58 15.88,61.58 16.51,60.95 A10.B2
N$232
  Bottom 0.254: A8.C1 13.97,56.5 14.61,55.87 25.4,55.87 26.04,56.5 A10.C1
N$233
  Bottom 0.254: A8.C2 7.62,57.77 8.26,58.41 19.05,58.41 19.69,57.77 A10.C2
N$234
  Bottom 0.254: A8.D1 10.8,53.32 11.43,52.69 22.23,52.69 22.86,53.32 A10.D1
N$235
  Bottom 0.254: A8.D2 4.45,54.59 5.08,55.23 15.88,55.23 16.51,54.59 A10.D2
N$236
  Bottom 0.254: A8.E1 13.97,50.15 14.61,49.52 25.4,49.52 26.04,50.15 A10.E1
N$237
  Bottom 0.254: A8.E2 7.62,51.42 8.26,52.05 19.05,52.05 19.69,51.42 A10.E2
N$238
  Bottom 0.254: A8.F1 10.8,46.98 11.43,46.34 22.23,46.34 22.86,46.98 A10.F1
N$239
  Bottom 0.254: A8.F2 4.45,48.24 5.08,48.88 15.88,48.88 16.51,48.24 A10.F2
N$240
  Bottom 0.254: A8.H1 13.97,43.8 14.61,43.16 25.4,43.16 26.04,43.8 A10.H1
N$241
  Bottom 0.254: A8.H2 7.62,45.07 8.26,45.7 19.05,45.7 19.69,45.07 A10.H2
N$242
  Bottom 0.254: A8.J1 10.8,40.62 11.43,39.99 22.23,39.99 22.86,40.62 A10.J1
N$243
  Bottom 0.254: A8.J2 4.45,41.89 5.08,42.53 15.88,42.53 16.51,41.89 A10.J2
N$244
  Bottom 0.254: A8.K1 13.97,37.45 14.61,36.81 25.4,36.81 26.04,37.45 A10.K1
N$245
  Bottom 0.254: A8.K2 7.62,38.72 8.26,39.35 19.05,39.35 19.69,38.72 A10.K2
N$246
  Bottom 0.254: A11.L1 36.2,34.27 36.83,33.64 47.62,33.64 48.26,34.27 A12.L1
N$247
  Bottom 0.254: A11.L2 29.85,35.55 30.48,36.18 41.28,36.18 41.91,35.55 A12.L2
N$248
  Bottom 0.254: A11.M1 39.37,31.1 40.01,30.46 50.8,30.46 51.44,31.1 A12.M1
N$249
  Bottom 0.254: A11.M2 33.02,32.37 33.66,33.01 44.45,33.01 45.09,32.37 A12.M2
N$250
  Bottom 0.254: A11.N1 36.2,27.92 36.83,27.29 47.62,27.29 48.26,27.92 A12.N1
N$251
  Bottom 0.254: A11.N2 29.85,29.2 30.48,29.83 41.28,29.83 41.91,29.2 A12.N2
N$252
  Bottom 0.254: A11.P1 39.37,24.75 40.01,24.11 50.8,24.11 51.44,24.75 A12.P1
N$253
  Bottom 0.254: A11.P2 33.02,26.02 33.66,26.65 44.45,26.65 45.09,26.02 A12.P2
N$254
  Bottom 0.254: A11.R1 36.2,21.57 36.83,20.94 47.62,20.94 48.26,21.57 A12.R1
N$255
  Bottom 0.254: A11.R2 29.85,22.84 30.48,23.48 41.28,23.48 41.91,22.84 A12.R2
N$256
  Bottom 0.254: A11.S1 39.37,18.4 40.01,17.77 50.8,17.77 51.44,18.4 A12.S1
N$257
  Bottom 0.254: A11.S2 33.02,19.67 33.66,20.3 44.45,20.3 45.09,19.67 A12.S2
N$258
  Bottom 0.254: A11.T1 36.2,15.22 36.83,14.59 47.62,14.59 48.26,15.22 A12.T1
N$259
  Bottom 0.254: A11.T2 29.85,16.49 30.48,17.13 41.28,17.13 41.91,16.49 A12.T2
N$260
  Bottom 0.254: A11.U1 39.37,12.05 40.01,11.41 50.8,11.41 51.44,12.05 A12.U1
N$261
  Bottom 0.254: A11.U2 33.02,13.32 33.66,13.95 44.45,13.95 45.09,13.32 A12.U2
N$262
  Bottom 0.254: A11.V1 36.2,8.88 36.83,8.24 47.62,8.24 48.26,8.88 A12.V1
N$263
  Bottom 0.254: A11.V2 29.85,10.14 30.48,10.78 41.28,10.78 41.91,10.14 A12.V2
N$264
  Bottom 0.254: A11.A1 39.37,62.85 40.01,62.21 50.8,62.21 51.44,62.85 A12.A1
N$265
  Bottom 0.254: A11.A2 33.02,64.12 33.66,64.76 44.45,64.76 45.09,64.12 A12.A2
N$266
  Bottom 0.254: A11.B1 36.2,59.68 36.83,59.04 47.62,59.04 48.26,59.68 A12.B1
N$267
  Bottom 0.254: A11.B2 29.85,60.95 30.48,61.58 41.28,61.58 41.91,60.95 A12.B2
N$268
  Bottom 0.254: A11.C1 39.37,56.5 40.01,55.87 50.8,55.87 51.44,56.5 A12.C1
N$269
  Bottom 0.254: A11.C2 33.02,57.77 33.66,58.41 44.45,58.41 45.09,57.77 A12.C2
N$270
  Bottom 0.254: A11.D1 36.2,53.32 36.83,52.69 47.62,52.69 48.26,53.32 A12.D1
N$271
  Bottom 0.254: A11.D2 29.85,54.59 30.48,55.23 41.28,55.23 41.91,54.59 A12.D2
N$272
  Bottom 0.254: A11.E1 39.37,50.15 40.01,49.52 50.8,49.52 51.44,50.15 A12.E1
N$273
  Bottom 0.254: A11.E2 33.02,51.42 33.66,52.05 44.45,52.05 45.09,51.42 A12.E2
N$274
  Bottom 0.254: A11.F1 36.2,46.98 36.83,46.34 47.62,46.34 48.26,46.98 A12.F1
N$275
  Bottom 0.254: A11.F2 29.85,48.24 30.48,48.88 41.28,48.88 41.91,48.24 A12.F2
N$276
  Bottom 0.254: A11.H1 39.37,43.8 40.01,43.16 50.8,43.16 51.44,43.8 A12.H1
N$277
  Bottom 0.254: A11.H2 33.02,45.07 33.66,45.7 44.45,45.7 45.09,45.07 A12.H2
N$278
  Bottom 0.254: A11.J1 36.2,40.62 36.83,39.99 47.62,39.99 48.26,40.62 A12.J1
N$279
  Bottom 0.254: A11.J2 29.85,41.89 30.48,42.53 41.28,42.53 41.91,41.89 A12.J2
N$280
  Bottom 0.254: A11.K1 39.37,37.45 40.01,36.81 50.8,36.81 51.44,37.45 A12.K1
N$281
  Bottom 0.254: A11.K2 33.02,38.72 33.66,39.35 44.45,39.35 45.09,38.72 A12.K2
OA1  (via drill 0.61)
  Top 0.254: A1-K1.18 66.04,66.66 67.31,67.93 JP1.1 | v66.67,98.41 67.31,99.05 67.31,104.76 68.58,106.03 67.95,106.67 67.95,107.94 69.22,109.21 IC1.3
  Bottom 0.254: v66.67,98.41 66.04,97.78 64.14,97.78 63.5,97.14 63.5,70.47 67.31,70.47 JP1.1
OB1
  Top 0.254: A1-K1.17 68.58,66.66 69.85,67.93 JP1.2 69.85,70.47 69.85,85.08 68.58,86.35 68.58,97.14 67.95,97.78 67.95,100.32 69.22,101.59 IC1.6
OB2
  Top 0.254: A2-K2.17 101.6,36.18 102.87,37.45 JP2.2
OC  (via drill 0.61)
  Top 0.254: v121.92,44.44 121.92,22.21 120.65,20.94 120.65,15.86 118.75,15.86 118.11,15.22 118.11,10.14 121.92,6.33 IN5-6.1 | v114.3,44.44 114.94,45.07 114.94,76.19 113.03,78.09 IC9.13
  Bottom 0.254: OC.1 95.89,80.63 97.16,79.36 99.69,79.36 IC9.8 100.97,80 102.87,81.9 110.49,81.9 112.4,80 IC9.13 | v121.92,44.44 v114.3,44.44
OC1  (via drill 0.61)
  Top 0.254: A1-K1.16 71.12,66.66 72.39,67.93 JP1.3 72.39,70.47 72.39,90.79 v73.66,92.06
  Bottom 0.254: v73.66,92.06 73.66,97.14 76.2,99.68 IC1.8
OD1  (via drill 0.61)
  Top 0.254: JP1.4 74.93,67.93 73.66,66.66 A1-K1.15 73.03,64.76 73.03,63.48 65.41,63.48 63.5,65.39 63.5,97.14 64.77,98.41 64.77,100.95 64.14,101.59 v64.14,108.57
  Bottom 0.254: v64.14,108.57 74.93,108.57 76.2,107.3 IC1.11
OD2  (via drill 0.61)
  Top 0.254: 106.68,36.18 107.95,37.45 JP2.4 | 106.68,36.18 A2-K2.15 106.68,36.18 | v120.65,88.25 120.65,90.79 121.92,92.06 121.92,97.14 122.56,97.78 122.56,100.32 121.28,101.59 IC5.6 | v130.81,80 v130.81,88.25 | v110.49,62.21 107.95,59.68 107.95,56.5 106.68,55.23 106.68,36.18
  Bottom 0.254: v130.81,88.25 v120.65,88.25 | v130.81,80 125.09,74.28 125.09,70.47 114.3,70.47 110.49,66.66 v110.49,62.21
OE1  (via drill 0.61)
  Top 0.254: A1-K1.14 76.2,66.66 77.47,67.93 JP1.5 77.47,70.47 74.93,73.01 v74.93,86.35 | v81.28,92.7 81.28,97.14 80.01,98.41 80.01,107.3 81.92,109.21 IC2.3
  Bottom 0.254: v74.93,86.35 v81.28,92.7
OE2  (via drill 0.61)
  Top 0.254: A2-K2.14 109.22,36.18 110.49,37.45 JP2.5 111.12,39.35 115.57,43.8 115.57,53.96 118.75,57.13 118.75,65.39 118.11,66.03 118.11,71.74 v118.75,72.38 | v128.27,78.73 128.27,85.08 129.54,86.35 129.54,98.41 128.91,99.05 IC5.8
  Bottom 0.254: v128.27,78.73 125.09,75.55 121.92,75.55 v118.75,72.38
OF1  (via drill 0.61)
  Top 0.254: A1-K1.13 78.74,66.66 80.01,67.93 JP1.6 80.01,70.47 80.01,92.7 v78.74,93.97
  Bottom 0.254: v78.74,93.97 78.74,97.14 79.38,97.78 84.45,97.78 84.45,100.32 83.19,101.59 IC2.6
OF2  (via drill 0.61)
  Top 0.254: A2-K2.13 111.76,36.18 113.03,37.45 JP2.6 | v144.14,106.03 148.59,101.59 148.59,34.91 v146.05,32.37
  Bottom 0.254: v144.14,106.03 130.81,106.03 129.54,107.3 IC5.11 | v146.05,32.37 114.3,32.37 112.4,34.27 A2-K2.13
OH1
  Top 0.254: JP1.7 82.55,67.93 81.28,66.66 A1-K1.12 81.28,64.12 81.28,63.48 84.45,63.48 85.09,64.12 85.09,66.66 86.36,67.93 86.36,70.47 87.63,71.74 87.63,85.08 88.9,86.35 88.9,98.41 89.53,99.05 IC2.8
OH2  (via drill 0.61)
  Top 0.254: A2-K2.12 114.3,36.18 115.57,37.45 JP2.7 | v130.18,103.49 130.18,106.67 132.72,109.21 IC6.3 | v145.42,70.47 146.05,69.84 146.05,34.91 v146.69,34.27
  Bottom 0.254: v130.18,103.49 134.62,103.49 140.34,97.78 141.61,97.78 145.42,93.97 v145.42,70.47 | v146.69,34.27 145.42,33.01 116.2,33.01 114.94,34.27 A2-K2.12
OJ1
  Top 0.254: A1-K1.11 83.82,66.66 85.09,67.93 JP1.8 85.09,70.47 85.09,88.89 86.36,90.16 86.36,97.14 88.27,99.05 88.27,105.4 89.53,106.67 IC2.11
OJ2  (via drill 0.61)
  Top 0.254: A2-K2.11 116.84,36.18 118.11,37.45 JP2.8 118.11,39.99 120.65,42.53 120.65,55.23 120.02,55.87 120.02,57.13 120.65,57.77 120.65,81.27 121.92,82.54 121.92,90.79 v123.19,92.06
  Bottom 0.254: v123.19,92.06 137.16,92.06 137.16,98.41 133.99,101.59 IC6.6
OK1  (via drill 0.61)
  Top 0.254: A1-K1.10 86.36,66.66 87.63,67.93 JP1.9 | v64.77,111.11 65.41,110.48 65.41,104.12 64.77,103.49 64.77,102.22 65.41,101.59 65.41,97.78 66.04,97.14 66.04,86.98 64.77,85.71 v64.77,80.63
  Bottom 0.254: v64.77,111.11 71.12,111.11 71.75,110.48 74.3,110.48 74.93,111.11 92.71,111.11 93.98,109.84 IC3.3 | v64.77,80.63 74.3,71.11 85.72,71.11 87,69.84 JP1.9
OK2  (via drill 0.61)
  Top 0.254: A2-K2.10 119.38,36.18 120.65,37.45 JP2.9 | v140.97,73.01 140.97,85.08 139.7,86.35 139.7,98.41 140.34,99.05 IC6.8 | v111.76,62.85 113.03,61.58 113.03,45.7 111.12,43.8 v111.12,41.89
  Bottom 0.254: v140.97,73.01 129.54,73.01 124.46,67.93 116.84,67.93 v111.76,62.85 | v111.12,41.89 112.4,40.62 118.75,40.62 120.02,39.35 JP2.9
OL1  (via drill 0.61)
  Top 0.254: L1-V1.18 91.44,66.66 90.17,67.93 JP1.10 90.17,70.47 90.17,80 93.98,83.81 93.98,93.33 92.71,94.6 92.71,100.32 v92.08,100.95
  Bottom 0.254: v92.08,100.95 92.71,100.95 93.98,102.22 IC3.6
OL2
  Top 0.254: L2-V2.18 124.46,36.18 123.19,37.45 JP2.10
  Bottom 0.254: IC6.11 142.24,107.3 146.05,107.3 148.59,104.76 148.59,36.81 126.36,36.81 125.09,35.55 L2-V2.18
OM1  (via drill 0.61)
  Top 0.254: L1-V1.17 93.98,66.66 92.71,67.93 JP1.11 92.71,70.47 92.71,81.27 v93.34,81.9 | v101.6,90.16 101.6,98.41 102.23,99.05 IC3.8
  Bottom 0.254: v101.6,90.16 81.28,90.16 79.38,88.25 78.11,88.25 77.47,87.62 77.47,85.71 89.53,85.71 v93.34,81.9
OM2  (via drill 0.61)
  Top 0.254: L2-V2.17 127,36.18 125.73,37.45 JP2.11 | v119.38,69.2 119.38,56.5 118.11,55.23 v118.11,50.15
  Bottom 0.254: v119.38,69.2 121.92,69.2 IC7.3 | v118.11,50.15 125.73,42.53 125.73,39.99 JP2.11
ON1  (via drill 0.61)
  Top 0.254: JP1.12 95.25,67.93 96.52,66.66 L1-V1.16 95.89,64.76 95.89,62.85 80.65,62.85 80.01,63.48 80.01,66.66 81.28,67.93 81.28,70.47 82.55,71.74 82.55,85.08 83.82,86.35 83.82,97.14 84.45,97.78 v84.45,103.49
  Bottom 0.254: v84.45,103.49 97.79,103.49 101.6,107.3 IC3.11
ON2  (via drill 0.61)
  Top 0.254: L2-V2.16 129.54,36.18 128.27,37.45 JP2.12 128.27,39.99 128.27,47.61 v124.46,51.42 | v121.28,57.13 121.28,59.68 122.56,60.95 IC7.6
  Bottom 0.254: v121.28,57.13 123.19,55.23 123.19,51.42 v124.46,51.42
OP1  (via drill 0.61)
  Top 0.254: JP1.13 97.79,67.93 99.06,66.66 L1-V1.15 99.06,64.12 99.06,63.48 107.31,63.48 107.95,64.12 107.95,66.66 106.68,67.93 106.68,88.25 109.22,90.79 v109.22,96.51 | v111.76,97.78 111.76,106.03 108.59,109.21 IC4.3
  Bottom 0.254: v111.76,97.78 110.49,96.51 v109.22,96.51
OP2
  Top 0.254: IC7.8 130.81,58.41 130.81,39.99 JP2.13 130.81,37.45 132.08,36.18 L2-V2.15
OR1  (via drill 0.61)
  Top 0.254: 101.6,66.66 100.33,67.93 JP1.14 | 101.6,66.66 L1-V1.14 101.6,66.66 | v124.46,89.52 v124.46,100.95 | 101.6,66.66 v101.6,85.08
  Bottom 0.254: v124.46,100.95 110.49,100.95 109.22,102.22 IC4.6 | v124.46,89.52 118.75,89.52 116.84,87.62 116.84,85.08 107.31,85.08 106.68,84.44 103.5,84.44 102.87,85.08 v101.6,85.08
OR2
  Top 0.254: L2-V2.14 134.62,36.18 133.35,37.45 JP2.14 133.35,39.99 133.35,65.39 132.08,66.66 IC7.11
OS1  (via drill 0.61)
  Top 0.254: L1-V1.13 104.14,66.66 102.87,67.93 JP1.15 | v118.75,78.09 120.02,79.36 120.02,86.98 116.84,90.16 116.84,98.41 116.2,99.05 IC4.8
  Bottom 0.254: v118.75,78.09 112.4,71.74 104.14,71.74 102.87,70.47 JP1.15
OS2  (via drill 0.61)
  Top 0.254: L2-V2.13 137.16,36.18 135.89,37.45 JP2.15 135.89,39.99 135.89,55.87 v136.53,56.5
  Bottom 0.254: v136.53,56.5 140.34,56.5 140.34,58.41 139.06,59.68 139.06,66.03 136.53,68.57 IC8.3
OT2  (via drill 0.61)
  Top 0.254: L2-V2.12 139.7,36.18 138.43,37.45 JP2.16 138.43,39.99 138.43,57.77 v139.06,58.41
  Bottom 0.254: v139.06,58.41 136.53,60.95 IC8.6
OU1  (via drill 0.61)
  Top 0.254: L1-V1.11 109.22,66.66 107.95,67.93 JP1.17 | v99.69,100.95 99.06,100.32 v99.06,71.11
  Bottom 0.254: v99.69,100.95 104.14,100.95 106.68,103.49 109.22,103.49 111.12,105.4 112.4,105.4 114.3,107.3 IC4.11 | v99.06,71.11 99.06,67.3 104.78,67.3 105.41,66.66 106.05,67.3 107.31,67.3 107.95,67.93 JP1.17
OU2
  Top 0.254: L2-V2.11 142.24,36.18 140.97,37.45 JP2.17 140.97,39.99 140.97,55.23 142.24,56.5 142.24,57.77 142.88,58.41 IC8.8
OV1  (via drill 0.61)
  Top 0.254: L1-V1.10 111.76,66.66 110.49,67.93 JP1.18 | v119.38,93.97 119.38,97.14 118.11,98.41 118.11,107.3 120.02,109.21 IC5.3 | v125.73,80.63 v125.73,93.33
  Bottom 0.254: v119.38,93.97 120.02,93.33 v125.73,93.33 | v125.73,80.63 116.2,71.11 112.4,71.11 111.12,69.84 JP1.18
OV2
  Top 0.254: IC8.11 144.14,66.03 145.42,64.76 145.42,57.13 143.51,55.23 143.51,39.99 JP2.18 143.51,37.45 144.78,36.18 L2-V2.10
P1
  Top 0.254: L1-V1.4 99.06,56.5 97.79,55.23 JP3.13 97.79,52.69 100.33,50.15 100.33,48.24 SIDE1.30 99.69,47.61 99.69,46.34 84.45,46.34 83.82,45.7 83.82,44.44 81.92,42.53 81.92,9.51 81.28,8.88 IN1-2.10
P2  (via drill 0.61)
  Top 0.254: L2-V2.4 132.08,26.02 130.81,24.75 JP4.13 130.81,22.21 130.81,19.04 129.54,17.77 SIDE2.24 | v113.03,18.4 113.03,13.95 110.49,11.41 110.49,7.6 111.76,6.33 IN3-4.13
  Bottom 0.254: v113.03,18.4 115.57,20.94 123.19,20.94 124.46,22.21 124.46,25.38 128.91,25.38 130.18,24.11 JP4.13
PIA-B5  (via drill 0.61)
  Top 0.254: v86.36,88.89 86.36,85.08 CORE-IO.18
  Bottom 0.254: v86.36,88.89 103.5,88.89 104.78,87.62 IC9.5
PIA-B7  (via drill 0.61)
  Top 0.254: v91.44,93.97 91.44,87.62 88.9,85.08 CORE-IO.20 | v111.76,95.23 111.76,89.52 113.03,88.25 IC9.2
  Bottom 0.254: IC9.2 113.66,86.35 114.94,86.35 IC9.1 | v91.44,93.97 92.71,95.23 v111.76,95.23
R1  (via drill 0.61)
  Top 0.254: L1-V1.5 101.6,56.5 100.33,55.23 JP3.14 | v86.36,27.92 86.36,11.41 83.82,8.88 IN1-2.12 | v107.95,43.8 v107.95,50.78
  Bottom 0.254: v86.36,27.92 102.23,43.8 v107.95,43.8 | v107.95,50.78 106.68,52.05 102.23,52.05 100.97,53.32 JP3.14 100.33,52.69 99.69,52.69 95.25,48.24 SIDE1.26
R2  (via drill 0.61)
  Top 0.254: L2-V2.5 134.62,26.02 133.35,24.75 JP4.14 133.35,22.21 132.08,20.94 132.08,17.77 SIDE2.26 132.08,16.49 130.81,15.22 v130.81,6.97
  Bottom 0.254: v130.81,6.97 121.28,6.97 120.65,6.33 115.57,6.33 114.94,5.7 IN3-4.15
S1  (via drill 0.61)
  Top 0.254: v80.01,12.05 78.74,13.32 78.74,55.23 77.47,56.5 77.47,59.04 78.11,59.68 104.14,59.68 104.14,59.04 L1-V1.6 104.14,56.5 102.87,55.23 JP3.15 102.87,52.69 102.87,48.24 SIDE1.32
  Bottom 0.254: v80.01,12.05 81.92,12.05 85.72,8.24 IN1-2.14
S2
  Top 0.254: L2-V2.6 137.16,26.02 135.89,24.75 JP4.15 135.89,22.21 135.89,19.04 134.62,17.77 SIDE2.28
  Bottom 0.254: IN3-4.10 106.68,7.6 105.41,6.33 105.41,2.53 139.7,2.53 144.78,7.6 144.78,25.38 139.06,25.38 137.8,26.65 L2-V2.6
T1
  Top 0.254: L1-V1.7 106.68,56.5 105.41,55.23 JP3.16 105.41,52.69 105.41,48.24 SIDE1.34
T2
  Top 0.254: L2-V2.7 139.7,26.02 138.43,24.75 JP4.16 138.43,22.21 137.16,20.94 137.16,17.77 SIDE2.30
  Bottom 0.254: IN3-4.12 109.22,8.88 109.22,12.05 121.28,12.05 123.19,13.95 123.19,18.4 135.25,18.4 136.53,17.13 SIDE2.30
U1
  Top 0.254: L1-V1.8 109.22,56.5 107.95,55.23 JP3.17
  Bottom 0.254: IN1-2.16 88.27,8.24 83.19,13.32 69.22,13.32 66.04,16.49 66.04,47.61 66.67,47.61 SIDE1.4 67.95,47.61 69.22,48.88 78.74,48.88 79.38,49.52 86.36,49.52 86.36,55.23 87,55.87 106.05,55.87 107.31,54.59 JP3.17
U2
  Top 0.254: L2-V2.8 142.24,26.02 140.97,24.75 JP4.17 140.97,22.21 142.24,20.94 142.24,17.77 SIDE2.34
  Bottom 0.254: IN3-4.14 112.4,8.24 114.94,10.78 135.25,10.78 138.43,13.95 138.43,15.86 140.34,15.86 141.61,17.13 SIDE2.34
V1
  Top 0.254: L1-V1.9 111.76,56.5 110.49,55.23 JP3.18 110.49,52.69 109.22,51.42 109.22,37.45 107.95,36.18 107.95,33.01 102.23,33.01 95.25,26.02 95.25,7.6 96.52,6.33 IN3-4.1
  Bottom 0.254: SIDE1.2 64.77,48.24 66.04,49.52 78.11,49.52 81.28,52.69 81.28,55.87 84.45,55.87 85.09,56.5 85.09,59.68 109.86,59.68 111.12,58.41 L1-V1.9
V2  (via drill 0.61)
  Top 0.254: L2-V2.9 144.78,26.02 143.51,24.75 JP4.18 143.51,22.21 143.51,13.95 140.97,11.41 | v138.43,4.43 140.97,4.43 140.97,11.41 | 140.97,11.41 140.97,15.22 139.7,16.49 SIDE2.32
  Bottom 0.254: v138.43,4.43 110.49,4.43 110.49,6.33 111.12,6.97 112.4,6.97 113.66,8.24 IN3-4.16
VCC  (via drill 0.61)
  Top 0.305: IC5.14 127.64,115.56 127,116.19 127,116.83 BYP5.1 | IC6.14 140.34,115.56 139.7,116.19 139.7,116.83 BYP6.1 | BYP4.1 114.3,116.83 114.94,116.19 114.94,115.56 IC4.14 | BYP3.1 101.6,116.83 102.23,116.19 102.23,115.56 IC3.14 | BYP1.1 76.2,116.83 76.84,116.19 76.84,115.56 IC1.14 | BYP2.1 88.9,116.83 89.53,116.19 89.53,115.56 IC2.14 | A2-K2.18 99.06,36.18 100.33,37.45 JP2.1 | BYP7.1 129.54,76.19 130.18,75.55 130.18,74.92 IC7.14 | BYP8.1 142.24,76.19 142.88,75.55 142.88,74.92 IC8.14 | RN1.1 115.57,90.79 114.3,89.52 114.3,81.9 115.57,80.63 IC9.14 115.57,78.09 115.57,60.31 v117.47,58.41
  Bottom 0.305: IC5.14 129.54,114.92 130.81,116.19 137.8,116.19 139.06,117.46 BYP6.1 | 87,116.19 80.01,116.19 78.74,114.92 IC1.14 76.2,114.92 74.93,113.65 65.41,113.65 62.23,110.48 62.23,99.68 67.31,99.68 68.58,98.41 68.58,90.79 77.47,90.79 | 87,116.19 88.27,117.46 BYP2.1 | 99.69,116.19 100.97,117.46 BYP3.1 | 87,116.19 99.69,116.19 | 99.69,116.19 112.4,116.19 113.66,117.46 BYP4.1 | BYP5.1 126.36,117.46 125.09,116.19 118.11,116.19 116.84,114.92 IC4.14 | 79.38,13.95 71.12,13.95 69.22,15.86 BYP10.1 | 79.38,13.95 90.81,13.95 92.08,15.22 POWER.2 | 79.38,13.95 88.9,23.48 | 88.9,23.48 99.06,33.64 A2-K2.18 | 140.97,90.79 140.97,77.46 | 140.97,90.79 140.97,94.6 RN4.1 | 140.97,77.46 142.24,77.46 BYP8.1 | 140.97,77.46 139.06,75.55 133.35,75.55 132.08,74.28 IC7.14 | 77.47,90.79 72.39,85.71 72.39,83.17 74.3,83.17 75.56,81.9 CORE-IO.9 | 77.47,90.79 80.65,93.97 88.27,93.97 89.53,95.23 RN3.1 | 76.84,81.9 78.74,83.81 CORE-IO.12 | 76.84,81.9 CORE-IO.9 | BYP9.1 117.47,80.63 116.84,80.63 116.2,80 IC9.14 114.94,78.73 111.76,75.55 83.19,75.55 76.84,81.9 | 117.47,53.32 120.65,50.15 140.97,50.15 144.14,53.32 RN2.1 | 117.47,53.32 v117.47,58.41 | 76.84,81.9 CORE-IO.9 | 140.97,90.79 115.57,90.79 RN1.1 | 88.9,23.48 85.09,27.29 85.09,34.27 88.9,34.27 99.06,44.44 99.06,49.52 113.66,49.52 117.47,53.32

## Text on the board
Top: Component Side | PA8PDP/VRS
Bottom: Solder Side
tValues: FlipChip Tester - Rev.1 | - | + | - | +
